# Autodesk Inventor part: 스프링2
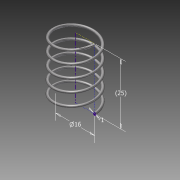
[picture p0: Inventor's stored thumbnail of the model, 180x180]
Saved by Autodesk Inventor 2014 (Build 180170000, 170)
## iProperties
Created: 2015-11
Part Number: 스프링2
Material: 강철, 탄소
Document SubType Name: Modeling
Designer: SEC
Mass: 1.5393 g
Surface Area: 7.90158 cm^2
Volume: 0.195591 cm^3
Density: 7.87 g/cm^3
Appearance: 반연마
Author: SEC
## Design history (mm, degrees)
sketch "스케치1"
  geometry: L1 (0, 0)-(8, 0); L2 (8, 0)-(8, 26); L3 (8, 26)-(0, 26); L4 (0, 26)-(0, 0); C1 r 0.5 at (8, 0)
  constraints: 8 end point, 2 parallel, 1 centre point, 1 coincident, 1 horizontal, 1 perpendicular
  dimensions: "d1" = 16 diameter of L2 L4; "d2" = 26 distance of L1.end L2.end (derived); "d3" = 1 diameter of C1
feature "코일1" pitch "d4" = 10; turns "d6" = 5; dims "d5" = 26 (= d2), "d7" = 0, angle "d8" = 90 deg, angle "d9" = 90 deg, "d10" = 0, "d11" = 0
sketch "스케치2"
  geometry: L1 (-8.5, 0)-(-7.5, 0) reference; 1 further point
  constraints: 1 horizontal alignment
extrude "돌출1" cut sketch "스케치2" stored distance "d12" = 10; taper "d13" = 0 deg
node "작업 평면2"
sketch "스케치3"
  geometry: L1 (0.5, 0)-(-0.5, 0) reference; 1 further point
  constraints: 1 horizontal alignment
extrude "돌출2" cut sketch "스케치3" stored distance "d15" = 10; taper "d16" = 0 deg
node "솔리드1"
node "절단 모서리 투영1"
node "절단 모서리 투영2"
other parameters: "d14" = 0
